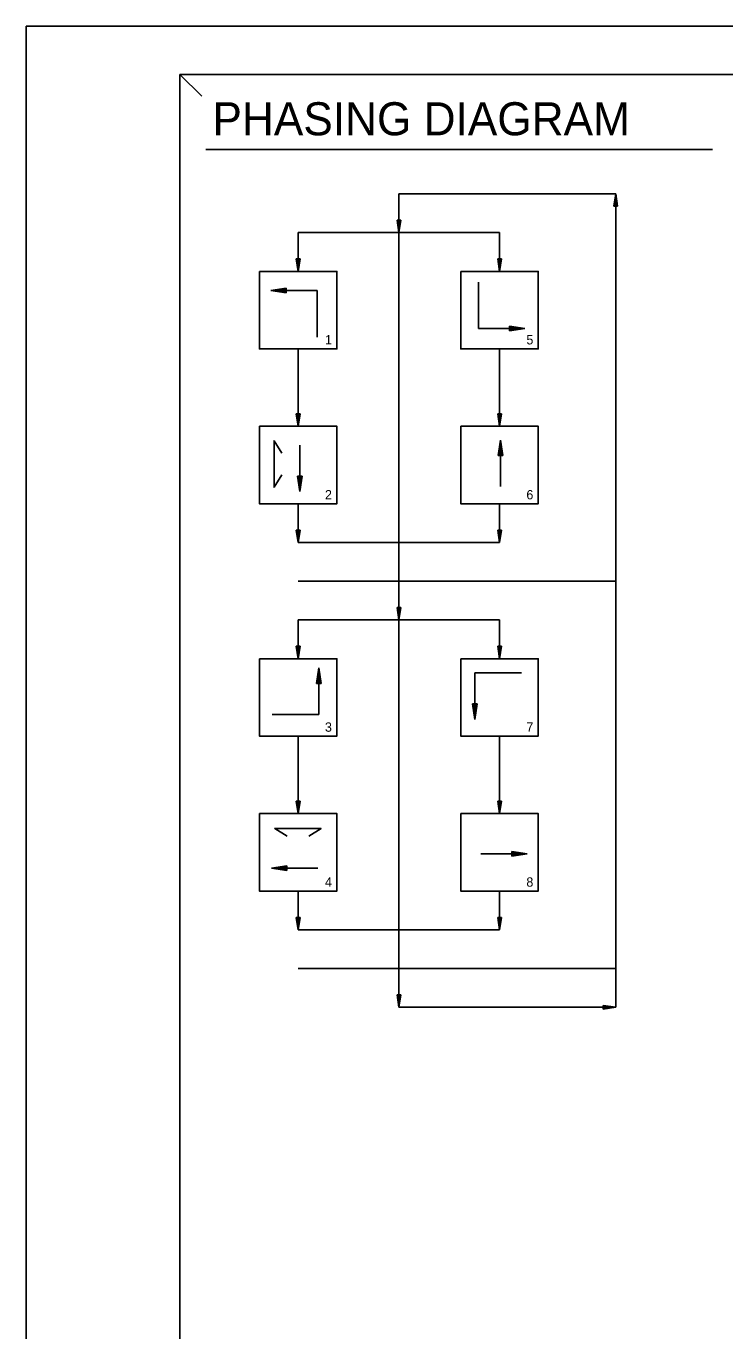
# Model space of a CAD drawing. Extents: x 635746 to 638310, y 744089 to 745312.
# Drawn here: x 635745.8 to 635886.7, y 745048.9 to 745312 of the extents above; entities that cross this region are included whole.
import ezdxf

# ---------------------------------------------------------------- set-up
doc = ezdxf.new("R2010")
doc.units = 0
for name, color, linetype in [('R_Border', 7, 'Continuous'), ('R_Draft', 7, 'Continuous'), ('R_Grid', 7, 'Continuous'), ('R_No Plot', 7, 'Continuous'), ('T_Drafting', 7, 'Continuous'), ('T_Notes', 7, 'Continuous')]:
    doc.layers.add(name, color=color, linetype=linetype)

msp = doc.modelspace()

# ---------------------------------------------------------------- linework, layer by layer
at = {"layer": 'R_Border'}
for p, q in [((635776.8, 745302.3), (636567.25, 745302.3)), ((635776.8, 744788.65), (635776.8, 745302.3))]:
    msp.add_line(p, q, dxfattribs=at)
at = {"layer": 'R_Draft'}
for p, q in [((635864.35, 745275.69), (635864.72, 745278.19)), ((635864.41, 745275.69), (635864.72, 745277.78)), ((635864.47, 745275.69), (635864.72, 745277.35)), ((635864.54, 745275.69), (635864.72, 745276.93)), ((635865.1, 745275.69), (635864.72, 745278.19)), ((635865.04, 745275.69), (635864.72, 745277.78)), ((635864.97, 745275.69), (635864.72, 745277.35)), ((635864.91, 745275.69), (635864.72, 745276.93)), ((635864.35, 745275.69), (635865.1, 745275.69)), ((635864.6, 745275.69), (635864.72, 745276.51)), ((635864.66, 745275.69), (635864.72, 745276.09)), ((635864.85, 745275.69), (635864.72, 745276.51)), ((635864.78, 745275.69), (635864.72, 745276.09)), ((635820.6, 745272.88), (635820.97, 745270.38)), ((635821.35, 745272.88), (635820.6, 745272.88)), ((635820.66, 745272.88), (635820.97, 745270.8)), ((635820.72, 745272.88), (635820.97, 745271.23)), ((635820.79, 745272.88), (635820.97, 745271.65)), ((635820.85, 745272.88), (635820.97, 745272.07)), ((635820.91, 745272.88), (635820.97, 745272.49)), ((635821.35, 745272.88), (635820.97, 745270.38)), ((635821.09, 745272.88), (635820.97, 745272.07)), ((635821.22, 745272.88), (635820.97, 745271.23)), ((635821.29, 745272.88), (635820.97, 745270.8)), ((635821.16, 745272.88), (635820.97, 745271.65)), ((635821.03, 745272.88), (635820.97, 745272.49)), ((635800.29, 745265.07), (635800.66, 745262.57)), ((635801.04, 745265.07), (635800.29, 745265.07)), ((635800.35, 745265.07), (635800.66, 745262.99)), ((635800.41, 745265.07), (635800.66, 745263.42)), ((635800.47, 745265.07), (635800.66, 745263.83)), ((635800.54, 745265.07), (635800.66, 745264.26)), ((635800.6, 745265.07), (635800.66, 745264.67)), ((635801.04, 745265.07), (635800.66, 745262.57)), ((635800.78, 745265.07), (635800.66, 745264.26)), ((635800.91, 745265.07), (635800.66, 745263.42)), ((635800.97, 745265.07), (635800.66, 745262.99)), ((635800.85, 745265.07), (635800.66, 745263.83)), ((635800.72, 745265.07), (635800.66, 745264.67)), ((635840.91, 745265.07), (635841.29, 745262.57)), ((635841.66, 745265.07), (635840.91, 745265.07)), ((635840.97, 745265.07), (635841.29, 745262.99)), ((635841.04, 745265.07), (635841.29, 745263.42)), ((635841.1, 745265.07), (635841.29, 745263.83)), ((635841.16, 745265.07), (635841.29, 745264.26)), ((635841.23, 745265.07), (635841.29, 745264.67)), ((635841.66, 745265.07), (635841.29, 745262.57)), ((635841.41, 745265.07), (635841.29, 745264.26)), ((635841.53, 745265.07), (635841.29, 745263.42)), ((635841.6, 745265.07), (635841.29, 745262.99)), ((635841.47, 745265.07), (635841.29, 745263.83)), ((635841.34, 745265.07), (635841.29, 745264.67)), ((635800.29, 745233.82), (635800.66, 745231.32)), ((635801.04, 745233.82), (635800.29, 745233.82)), ((635800.35, 745233.82), (635800.66, 745231.74)), ((635800.41, 745233.82), (635800.66, 745232.17)), ((635800.47, 745233.82), (635800.66, 745232.58)), ((635800.54, 745233.82), (635800.66, 745233.01)), ((635800.6, 745233.82), (635800.66, 745233.42)), ((635801.04, 745233.82), (635800.66, 745231.32)), ((635800.78, 745233.82), (635800.66, 745233.01)), ((635800.91, 745233.82), (635800.66, 745232.17)), ((635800.97, 745233.82), (635800.66, 745231.74)), ((635800.85, 745233.82), (635800.66, 745232.58)), ((635800.72, 745233.82), (635800.66, 745233.42)), ((635840.91, 745233.82), (635841.29, 745231.32)), ((635841.66, 745233.82), (635840.91, 745233.82)), ((635840.97, 745233.82), (635841.29, 745231.74)), ((635841.04, 745233.82), (635841.29, 745232.17)), ((635841.1, 745233.82), (635841.29, 745232.58)), ((635841.16, 745233.82), (635841.29, 745233.01)), ((635841.23, 745233.82), (635841.29, 745233.42)), ((635841.66, 745233.82), (635841.29, 745231.32)), ((635841.41, 745233.82), (635841.29, 745233.01)), ((635841.53, 745233.82), (635841.29, 745232.17)), ((635841.6, 745233.82), (635841.29, 745231.74)), ((635841.47, 745233.82), (635841.29, 745232.58)), ((635841.34, 745233.82), (635841.29, 745233.42)), ((635800.29, 745210.38), (635800.66, 745207.88)), ((635801.04, 745210.38), (635800.29, 745210.38)), ((635800.35, 745210.38), (635800.66, 745208.3)), ((635800.41, 745210.38), (635800.66, 745208.73)), ((635800.47, 745210.38), (635800.66, 745209.15)), ((635800.54, 745210.38), (635800.66, 745209.57)), ((635800.6, 745210.38), (635800.66, 745209.99)), ((635801.04, 745210.38), (635800.66, 745207.88)), ((635800.78, 745210.38), (635800.66, 745209.57)), ((635800.91, 745210.38), (635800.66, 745208.73)), ((635800.97, 745210.38), (635800.66, 745208.3)), ((635800.85, 745210.38), (635800.66, 745209.15)), ((635800.72, 745210.38), (635800.66, 745209.99)), ((635840.91, 745210.38), (635841.29, 745207.88)), ((635841.66, 745210.38), (635840.91, 745210.38)), ((635840.97, 745210.38), (635841.29, 745208.3)), ((635841.04, 745210.38), (635841.29, 745208.73)), ((635841.1, 745210.38), (635841.29, 745209.15)), ((635841.16, 745210.38), (635841.29, 745209.57)), ((635841.23, 745210.38), (635841.29, 745209.99)), ((635841.66, 745210.38), (635841.29, 745207.88)), ((635841.41, 745210.38), (635841.29, 745209.57)), ((635841.53, 745210.38), (635841.29, 745208.73)), ((635841.6, 745210.38), (635841.29, 745208.3)), ((635841.47, 745210.38), (635841.29, 745209.15)), ((635841.34, 745210.38), (635841.29, 745209.99)), ((635820.6, 745194.76), (635820.97, 745192.26)), ((635821.35, 745194.76), (635820.6, 745194.76)), ((635820.66, 745194.76), (635820.97, 745192.67)), ((635820.72, 745194.76), (635820.97, 745193.1)), ((635820.79, 745194.76), (635820.97, 745193.52)), ((635820.85, 745194.76), (635820.97, 745193.94)), ((635820.91, 745194.76), (635820.97, 745194.36)), ((635821.35, 745194.76), (635820.97, 745192.26)), ((635821.09, 745194.76), (635820.97, 745193.94)), ((635821.22, 745194.76), (635820.97, 745193.1)), ((635821.29, 745194.76), (635820.97, 745192.67)), ((635821.16, 745194.76), (635820.97, 745193.52)), ((635821.03, 745194.76), (635820.97, 745194.36)), ((635800.29, 745186.94), (635800.66, 745184.44)), ((635801.04, 745186.94), (635800.29, 745186.94)), ((635800.35, 745186.94), (635800.66, 745184.86)), ((635800.41, 745186.94), (635800.66, 745185.29)), ((635800.47, 745186.94), (635800.66, 745185.71)), ((635800.54, 745186.94), (635800.66, 745186.13)), ((635800.6, 745186.94), (635800.66, 745186.55)), ((635801.04, 745186.94), (635800.66, 745184.44)), ((635800.78, 745186.94), (635800.66, 745186.13)), ((635800.91, 745186.94), (635800.66, 745185.29)), ((635800.97, 745186.94), (635800.66, 745184.86)), ((635800.85, 745186.94), (635800.66, 745185.71)), ((635800.72, 745186.94), (635800.66, 745186.55)), ((635840.91, 745186.94), (635841.29, 745184.44)), ((635841.66, 745186.94), (635840.91, 745186.94)), ((635840.97, 745186.94), (635841.29, 745184.86)), ((635841.04, 745186.94), (635841.29, 745185.29)), ((635841.1, 745186.94), (635841.29, 745185.71)), ((635841.16, 745186.94), (635841.29, 745186.13)), ((635841.23, 745186.94), (635841.29, 745186.55)), ((635841.66, 745186.94), (635841.29, 745184.44)), ((635841.41, 745186.94), (635841.29, 745186.13)), ((635841.53, 745186.94), (635841.29, 745185.29)), ((635841.6, 745186.94), (635841.29, 745184.86)), ((635841.47, 745186.94), (635841.29, 745185.71)), ((635841.34, 745186.94), (635841.29, 745186.55)), ((635800.29, 745155.69), (635800.66, 745153.19)), ((635801.04, 745155.69), (635800.29, 745155.69)), ((635800.35, 745155.69), (635800.66, 745153.61)), ((635800.41, 745155.69), (635800.66, 745154.04)), ((635800.47, 745155.69), (635800.66, 745154.46)), ((635800.54, 745155.69), (635800.66, 745154.88)), ((635800.6, 745155.69), (635800.66, 745155.3)), ((635801.04, 745155.69), (635800.66, 745153.19)), ((635800.78, 745155.69), (635800.66, 745154.88)), ((635800.91, 745155.69), (635800.66, 745154.04)), ((635800.97, 745155.69), (635800.66, 745153.61)), ((635800.85, 745155.69), (635800.66, 745154.46)), ((635800.72, 745155.69), (635800.66, 745155.3)), ((635840.91, 745155.69), (635841.29, 745153.19)), ((635841.66, 745155.69), (635840.91, 745155.69)), ((635840.97, 745155.69), (635841.29, 745153.61)), ((635841.04, 745155.69), (635841.29, 745154.04)), ((635841.1, 745155.69), (635841.29, 745154.46)), ((635841.16, 745155.69), (635841.29, 745154.88)), ((635841.23, 745155.69), (635841.29, 745155.3)), ((635841.66, 745155.69), (635841.29, 745153.19)), ((635841.41, 745155.69), (635841.29, 745154.88)), ((635841.53, 745155.69), (635841.29, 745154.04)), ((635841.6, 745155.69), (635841.29, 745153.61)), ((635841.47, 745155.69), (635841.29, 745154.46)), ((635841.34, 745155.69), (635841.29, 745155.3)), ((635800.29, 745132.26), (635800.66, 745129.76)), ((635801.04, 745132.26), (635800.29, 745132.26)), ((635800.35, 745132.26), (635800.66, 745130.17)), ((635800.41, 745132.26), (635800.66, 745130.6)), ((635800.47, 745132.26), (635800.66, 745131.02)), ((635800.54, 745132.26), (635800.66, 745131.44)), ((635800.6, 745132.26), (635800.66, 745131.86)), ((635801.04, 745132.26), (635800.66, 745129.76)), ((635800.78, 745132.26), (635800.66, 745131.44)), ((635800.91, 745132.26), (635800.66, 745130.6)), ((635800.97, 745132.26), (635800.66, 745130.17)), ((635800.85, 745132.26), (635800.66, 745131.02)), ((635800.72, 745132.26), (635800.66, 745131.86)), ((635840.91, 745132.26), (635841.29, 745129.76)), ((635841.66, 745132.26), (635840.91, 745132.26)), ((635840.97, 745132.26), (635841.29, 745130.17)), ((635841.04, 745132.26), (635841.29, 745130.6)), ((635841.1, 745132.26), (635841.29, 745131.02)), ((635841.16, 745132.26), (635841.29, 745131.44)), ((635841.23, 745132.26), (635841.29, 745131.86)), ((635841.66, 745132.26), (635841.29, 745129.76)), ((635841.41, 745132.26), (635841.29, 745131.44)), ((635841.53, 745132.26), (635841.29, 745130.6)), ((635841.6, 745132.26), (635841.29, 745130.17)), ((635841.47, 745132.26), (635841.29, 745131.02)), ((635841.34, 745132.26), (635841.29, 745131.86)), ((635820.6, 745116.63), (635820.97, 745114.13)), ((635821.35, 745116.63), (635820.6, 745116.63)), ((635820.66, 745116.63), (635820.97, 745114.55)), ((635820.72, 745116.63), (635820.97, 745114.98)), ((635820.79, 745116.63), (635820.97, 745115.4)), ((635820.85, 745116.63), (635820.97, 745115.82)), ((635820.91, 745116.63), (635820.97, 745116.24)), ((635821.35, 745116.63), (635820.97, 745114.13)), ((635821.09, 745116.63), (635820.97, 745115.82)), ((635821.22, 745116.63), (635820.97, 745114.98)), ((635821.29, 745116.63), (635820.97, 745114.55)), ((635821.16, 745116.63), (635820.97, 745115.4)), ((635821.03, 745116.63), (635820.97, 745116.24)), ((635862.22, 745114.51), (635864.72, 745114.13)), ((635862.22, 745114.51), (635862.22, 745113.76)), ((635862.22, 745114.44), (635864.31, 745114.13)), ((635862.22, 745114.38), (635863.88, 745114.13)), ((635862.22, 745114.32), (635863.46, 745114.13)), ((635862.22, 745114.25), (635863.04, 745114.13)), ((635862.22, 745114.19), (635862.62, 745114.13)), ((635862.22, 745113.76), (635864.72, 745114.13)), ((635862.22, 745114.01), (635863.04, 745114.13)), ((635862.22, 745113.88), (635863.88, 745114.13)), ((635862.22, 745113.82), (635864.31, 745114.13)), ((635862.22, 745113.95), (635863.46, 745114.13)), ((635862.22, 745114.07), (635862.62, 745114.13))]:
    msp.add_line(p, q, dxfattribs=at)
at = {"layer": 'R_Grid'}
msp.add_line((635776.8, 745302.3), (635781.22, 745297.88), dxfattribs=at)
at = {"layer": 'R_No Plot'}
msp.add_line((635745.8, 745312.04), (636579.13, 745312.04), dxfattribs=at)
msp.add_lwpolyline([(635745.78, 745312.04), (636579.13, 745312.04), (636579.13, 744778.69), (635745.78, 744778.69)], close=True, dxfattribs=at)
at = {"layer": 'T_Drafting'}
for p, q in [((635820.97, 745114.13), (635820.97, 745278.19)), ((635820.97, 745278.19), (635864.72, 745278.19)), ((635864.72, 745278.19), (635864.72, 745114.13)), ((635800.66, 745262.57), (635800.66, 745270.38)), ((635800.66, 745270.38), (635841.29, 745270.38)), ((635841.29, 745262.57), (635841.29, 745270.38)), ((635795.13, 745258.7), (635798.25, 745259.16)), ((635804.5, 745258.7), (635795.13, 745258.7)), ((635798.25, 745258.23), (635795.13, 745258.7)), ((635798.25, 745259.09), (635795.65, 745258.7)), ((635795.65, 745258.7), (635798.25, 745258.3)), ((635796.19, 745258.7), (635798.25, 745259.01)), ((635798.25, 745258.38), (635796.19, 745258.7)), ((635798.25, 745258.93), (635796.71, 745258.7)), ((635796.71, 745258.7), (635798.25, 745258.46)), ((635797.24, 745258.7), (635798.25, 745258.85)), ((635798.25, 745258.54), (635797.24, 745258.7)), ((635798.25, 745258.77), (635797.76, 745258.7)), ((635797.76, 745258.7), (635798.25, 745258.62)), ((635798.25, 745258.23), (635798.25, 745259.16)), ((635804.5, 745249.32), (635804.5, 745258.7)), ((635837.04, 745260.4), (635837.04, 745251.03)), ((635837.04, 745251.03), (635846.41, 745251.03)), ((635843.29, 745251.49), (635846.41, 745251.03)), ((635843.29, 745251.49), (635843.29, 745250.56)), ((635845.89, 745251.03), (635843.29, 745251.42)), ((635843.29, 745251.34), (635845.35, 745251.03)), ((635844.83, 745251.03), (635843.29, 745251.26)), ((635843.29, 745251.18), (635844.3, 745251.03)), ((635843.78, 745251.03), (635843.29, 745251.1)), ((635846.41, 745251.03), (635843.29, 745250.56)), ((635843.29, 745250.63), (635845.89, 745251.03)), ((635845.35, 745251.03), (635843.29, 745250.71)), ((635843.29, 745250.79), (635844.83, 745251.03)), ((635844.3, 745251.03), (635843.29, 745250.87)), ((635843.29, 745250.95), (635843.78, 745251.03)), ((635800.66, 745231.32), (635800.66, 745246.94)), ((635841.29, 745231.32), (635841.29, 745246.94)), ((635800.98, 745227.53), (635800.98, 745218.15)), ((635841.04, 745225.42), (635841.51, 745228.55)), ((635841.51, 745228.03), (635841.12, 745225.42)), ((635841.2, 745225.42), (635841.51, 745227.49)), ((635841.51, 745226.97), (635841.28, 745225.42)), ((635841.51, 745219.17), (635841.51, 745228.55)), ((635841.51, 745228.55), (635841.98, 745225.42)), ((635841.9, 745225.42), (635841.51, 745228.03)), ((635841.51, 745227.49), (635841.82, 745225.42)), ((635841.75, 745225.42), (635841.51, 745226.97)), ((635841.04, 745225.42), (635841.98, 745225.42)), ((635841.36, 745225.42), (635841.51, 745226.44)), ((635841.51, 745225.92), (635841.44, 745225.42)), ((635841.51, 745226.44), (635841.67, 745225.42)), ((635841.59, 745225.42), (635841.51, 745225.92)), ((635800.98, 745218.15), (635800.51, 745221.28)), ((635801.44, 745221.28), (635800.51, 745221.28)), ((635800.59, 745221.28), (635800.98, 745218.67)), ((635800.98, 745219.21), (635800.67, 745221.28)), ((635800.74, 745221.28), (635800.98, 745219.73)), ((635800.98, 745220.26), (635800.82, 745221.28)), ((635800.9, 745221.28), (635800.98, 745220.78)), ((635800.98, 745220.78), (635801.05, 745221.28)), ((635801.13, 745221.28), (635800.98, 745220.26)), ((635800.98, 745219.73), (635801.21, 745221.28)), ((635801.29, 745221.28), (635800.98, 745219.21)), ((635800.98, 745218.67), (635801.37, 745221.28)), ((635801.44, 745221.28), (635800.98, 745218.15)), ((635800.66, 745207.88), (635800.66, 745215.69)), ((635841.29, 745207.88), (635841.29, 745215.69)), ((635800.66, 745207.88), (635841.29, 745207.88)), ((635800.66, 745200.07), (635864.72, 745200.07)), ((635800.66, 745192.26), (635841.29, 745192.26)), ((635800.66, 745184.44), (635800.66, 745192.26)), ((635841.29, 745184.44), (635841.29, 745192.26)), ((635804.34, 745179.46), (635804.81, 745182.59)), ((635804.81, 745173.21), (635804.81, 745182.59)), ((635804.81, 745182.59), (635805.28, 745179.46)), ((635804.81, 745182.06), (635804.42, 745179.46)), ((635804.5, 745179.46), (635804.81, 745181.53)), ((635804.81, 745181.01), (635804.58, 745179.46)), ((635804.66, 745179.46), (635804.81, 745180.48)), ((635804.81, 745179.95), (635804.74, 745179.46)), ((635805.2, 745179.46), (635804.81, 745182.06)), ((635804.81, 745181.53), (635805.12, 745179.46)), ((635805.04, 745179.46), (635804.81, 745181.01)), ((635804.81, 745180.48), (635804.97, 745179.46)), ((635804.89, 745179.46), (635804.81, 745179.95)), ((635845.69, 745181.56), (635836.31, 745181.56)), ((635836.31, 745181.56), (635836.31, 745172.19)), ((635804.34, 745179.46), (635805.28, 745179.46)), ((635836.31, 745172.19), (635835.85, 745175.31)), ((635836.78, 745175.31), (635835.85, 745175.31)), ((635835.92, 745175.31), (635836.31, 745172.71)), ((635836.31, 745173.25), (635836, 745175.31)), ((635836.08, 745175.31), (635836.31, 745173.77)), ((635836.31, 745174.3), (635836.16, 745175.31)), ((635836.24, 745175.31), (635836.31, 745174.82)), ((635836.31, 745174.82), (635836.39, 745175.31)), ((635836.47, 745175.31), (635836.31, 745174.3)), ((635836.31, 745173.77), (635836.55, 745175.31)), ((635836.63, 745175.31), (635836.31, 745173.25)), ((635836.31, 745172.71), (635836.71, 745175.31)), ((635836.78, 745175.31), (635836.31, 745172.19)), ((635795.44, 745173.21), (635804.81, 745173.21)), ((635800.66, 745153.19), (635800.66, 745168.82)), ((635841.29, 745153.19), (635841.29, 745168.82)), ((635843.76, 745145.55), (635846.89, 745145.09)), ((635843.76, 745145.55), (635843.76, 745144.62)), ((635846.37, 745145.09), (635843.76, 745145.48)), ((635843.76, 745145.4), (635845.83, 745145.09)), ((635845.31, 745145.09), (635843.76, 745145.32)), ((635795.26, 745142.21), (635798.39, 745142.68)), ((635798.39, 745141.74), (635798.39, 745142.68)), ((635837.51, 745145.09), (635846.89, 745145.09)), ((635843.76, 745145.24), (635844.78, 745145.09)), ((635844.26, 745145.09), (635843.76, 745145.16)), ((635846.89, 745145.09), (635843.76, 745144.62)), ((635843.76, 745144.69), (635846.37, 745145.09)), ((635845.83, 745145.09), (635843.76, 745144.77)), ((635843.76, 745144.85), (635845.31, 745145.09)), ((635844.78, 745145.09), (635843.76, 745144.93)), ((635843.76, 745145.01), (635844.26, 745145.09)), ((635804.64, 745142.21), (635795.26, 745142.21)), ((635798.39, 745141.74), (635795.26, 745142.21)), ((635798.39, 745142.6), (635795.78, 745142.21)), ((635795.78, 745142.21), (635798.39, 745141.82)), ((635796.32, 745142.21), (635798.39, 745142.52)), ((635798.39, 745141.9), (635796.32, 745142.21)), ((635798.39, 745142.45), (635796.84, 745142.21)), ((635796.84, 745142.21), (635798.39, 745141.98)), ((635797.37, 745142.21), (635798.39, 745142.37)), ((635798.39, 745142.06), (635797.37, 745142.21)), ((635798.39, 745142.29), (635797.89, 745142.21)), ((635797.89, 745142.21), (635798.39, 745142.14)), ((635800.66, 745129.76), (635800.66, 745137.57)), ((635841.29, 745129.76), (635841.29, 745137.57)), ((635800.66, 745129.76), (635841.29, 745129.76)), ((635800.66, 745121.94), (635864.72, 745121.94)), ((635820.97, 745114.13), (635864.72, 745114.13))]:
    msp.add_line(p, q, dxfattribs=at)
for points in [[(635792.85, 745262.57), (635808.47, 745262.57), (635808.47, 745246.94), (635792.85, 745246.94)], [(635833.47, 745262.57), (635849.1, 745262.57), (635849.1, 745246.94), (635833.47, 745246.94)], [(635792.85, 745231.32), (635808.47, 745231.32), (635808.47, 745215.69), (635792.85, 745215.69)], [(635833.47, 745231.32), (635849.1, 745231.32), (635849.1, 745215.69), (635833.47, 745215.69)], [(635792.85, 745184.44), (635808.47, 745184.44), (635808.47, 745168.82), (635792.85, 745168.82)], [(635833.47, 745184.44), (635849.1, 745184.44), (635849.1, 745168.82), (635833.47, 745168.82)], [(635792.85, 745153.19), (635808.47, 745153.19), (635808.47, 745137.57), (635792.85, 745137.57)], [(635833.47, 745153.19), (635849.1, 745153.19), (635849.1, 745137.57), (635833.47, 745137.57)]]:
    msp.add_lwpolyline(points, close=True, dxfattribs=at)
for points in [[(635797.38, 745221.52), (635795.81, 745219.02), (635795.81, 745228.39), (635797.38, 745225.89)], [(635798.43, 745148.64), (635795.93, 745150.2), (635805.3, 745150.2), (635802.8, 745148.64)]]:
    msp.add_lwpolyline(points, dxfattribs=at)
at = {"layer": 'T_Notes'}
msp.add_line((635782.03, 745287.12), (635884.24, 745287.12), dxfattribs=at)

# ---------------------------------------------------------------- texts
for s, height, p in [('PHASING DIAGRAM', 6.6667, (635783.37, 745290.01)), ('1', 1.88, (635806.07, 745247.83)), ('5', 1.88, (635846.7, 745247.83)), ('2', 1.88, (635806.07, 745216.58)), ('6', 1.88, (635846.7, 745216.58)), ('3', 1.88, (635806.07, 745169.71)), ('7', 1.88, (635846.7, 745169.71)), ('4', 1.88, (635806.07, 745138.46)), ('8', 1.88, (635846.7, 745138.46))]:
    msp.add_text(s, height=height, rotation=360, dxfattribs=at).set_placement(p)

doc.saveas('drawing.dxf')
